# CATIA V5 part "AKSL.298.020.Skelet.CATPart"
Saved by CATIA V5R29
Part number: АКСЛ.298.000.Skelet
Publications: "S металла", "R гиба", "K factor", "OutputPlane.1 (Line.4)", "1 угол Profile.1", "2 угол Profile.2", "угол 1Profile.3", "угол 2Profile.4", "Extrude.1", "Extrude.2", "Profile.5", "Profile.6", "Plane.1", "Вертикальный уголок1 Sweep.1", "Вертикальный уголок2 Sweep.2", "ПЛТ середина вертикали Plane.9", "Положение ребра", "Отрезка Plane.11"
Bounding box of the stored display mesh (mm): x -250 to 300, y -300 to 52, z -248 to 52
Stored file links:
  Z:\ООО Аксель\Соединения бруса\Соединения бруса\Соединения из листа\АКСЛ.298.020 (Дуо)\AKSL.298.020.Skelet.CATPart
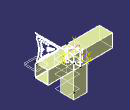
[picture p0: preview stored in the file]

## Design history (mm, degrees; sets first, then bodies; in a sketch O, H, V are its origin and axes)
Parameters
  `S металла` = 2 mm
  `R гиба` = 1.9 mm
  `K factor` = 0.49
  `Положение ребра` = 12 mm
Set1
  Extrude1: Element1 Sketch3.C1, Lim1 300, Lim2 100, Direction yz-plane, FirstUpto Plane2, SecondUpto Plane10
  Extrude2: Element1 Sketch3.C2, Lim1 300, Lim2 100, Direction yz-plane, FirstUpto Plane2, SecondUpto Plane10
  Plane1: type Offset, RefPlane yz-plane, Offset 52, reversed
  Plane2: type Offset, RefPlane Plane1, Offset 302
  Line1: type PtDir, RefPoint vertex [face of Extrude1], Direction zx-plane, Start 0, End 20
  Plane3: type 2Lines, Element1 Line1, Element2 edge of Extrude1
  Plane4: type Offset, RefPlane Plane3, Offset 12 {= `Положение ребра`}, reversed
  Sketch1 on Plane4, origin (0, 0, 40), H (1, 0, 0), V (0, 1, 0)
    line L1 (95.2986, -93.8989) -> (95.1702, -93.8708)
    line L2 (103.7348, -92.0951) -> (103.8404, -92.1505)
    line L3 (100.9137, -95.8319) -> (100.7931, -95.8772)
    line L4 (88.0721, -100.8486) -> (88.0277, -100.9705)
    line L5 (101.0187, -95.7527) -> (100.9137, -95.8319)
    circle A1 centre (68.6729, -176.9877) radius 4
    line L6 (87.0077, -111.8036) -> (86.7739, -111.2916)
    line L7 (75.3598, -82.5251) -> (75.142, -82.5472)
    line L8 (72.312, -80.0992) -> (72.247, -79.8958)
    line L9 (72.2211, -79.6855) -> (72.2342, -79.4741)
    line L10 (80.7946, -95.0346) -> (80.6807, -94.9619)
    line L11 (84.2807, -91.5755) -> (84.3166, -91.7324)
    line L12 (89.731, -91.801) -> (84.4045, -89.8059)
    line L13 (88.0384, -113.0845) -> (87.6445, -112.704)
    line L14 (83.0187, -99.498) -> (89.8948, -92.5474)
    line L15 (77.274, -85.8262) -> (77.3517, -85.7209)
    line L16 (91.1213, -114.1413) -> (90.5663, -114.1308)
    circle A2 centre (161.1601, -67.4127) radius 4
    line L17 (94.082, -112.8251) -> (93.6617, -113.1999)
    line L18 (103.9239, -92.227) -> (104.0205, -92.4228)
    line L19 (80.6807, -94.9619) -> (80.5861, -94.8608)
    line L20 (84.3067, -91.89) -> (84.2531, -92.0385)
    line L21 (94.921, -93.9256) -> (94.816, -94.0048)
    line L22 (88.1508, -100.7421) -> (88.0721, -100.8486)
    line L23 (108.5562, -90.1261) -> (108.3766, -90.0333)
    line L24 (83.8456, -90.0121) -> (83.8, -90.1301)
    line L25 (81.1886, -95.0686) -> (81.0549, -95.0893)
    line L26 (100.5369, -95.8592) -> (95.2986, -93.8989)
    line L27 (78.6809, -79.6446) -> (78.4822, -79.7363)
    line L28 (109.7605, -85.4744) -> (111.5707, -86.1022)
    line L29 (78.2968, -79.8563) -> (78.1279, -80.0039)
    line L30 (95.0417, -93.8803) -> (94.921, -93.9256)
    circle A3 centre (68.759, -192.9874) radius 4
    line L31 (90.0105, -92.3482) -> (90.0158, -92.1298)
    line L32 (227.6727, -52) -> (214.923, -71.1234)
    line L33 (79.8354, -83.3132) -> (79.9633, -83.3033)
    line L34 (78.1279, -80.0039) -> (75.9468, -82.2087)
    line L35 (95.1702, -93.8708) -> (95.0417, -93.8803)
    line L36 (104.0153, -92.6413) -> (103.9717, -92.746)
    line L37 (74.5134, -82.3628) -> (74.3336, -82.2176)
    circle A4 centre (141.0249, -107.9229) radius 4
    line L38 (80.5171, -94.7326) -> (77.2497, -86.203)
    line L39 (84.2531, -92.0385) -> (84.1575, -92.1683)
    circle A5 centre (108.8779, -140.4178) radius 4
    line L40 (91.7315, -108.3715) -> (91.8906, -108.2474)
    circle A6 centre (145.1604, -67.4988) radius 4
    line L41 (104.0205, -92.4228) -> (104.0153, -92.6413)
    line L42 (91.3701, -108.4755) -> (91.5551, -108.4469)
    line L43 (93.2043, -113.5149) -> (92.7158, -113.7683)
    circle A7 centre (177.1599, -67.3266) radius 4
    line L44 (88.0492, -101.2285) -> (90.6258, -107.9813)
    line L45 (108.8018, -90.4119) -> (108.6986, -90.2553)
    line L46 (91.0099, -108.3996) -> (91.1854, -108.4591)
    line L47 (77.2299, -85.9469) -> (77.274, -85.8262)
    line L48 (90.0092, -114.0498) -> (89.4664, -113.8998)
    line L49 (84.3166, -91.7324) -> (84.3067, -91.89)
    line L50 (72.559, -80.462) -> (72.416, -80.2899)
    line L51 (88.0277, -100.9705) -> (88.0194, -101.0997)
    line L52 (93.6617, -113.1999) -> (93.2043, -113.5149)
    circle A8 centre (96.5188, -154.9182) radius 4
    line L53 (87.2994, -112.2757) -> (87.0077, -111.8036)
    line L54 (74.924, -82.5276) -> (74.7123, -82.4661)
    line L55 (114.0524, -88.2338) -> (114.2803, -88.7469)
    arc A9 centre (434.9713, -430.8711) radius 421.7104 from (214.923, -71.1234) to (72.876, -214.7077) ccw
    line L56 (75.142, -82.5472) -> (74.924, -82.5276)
    line L57 (92.7158, -113.7683) -> (92.2019, -113.9584)
    line L58 (72.3779, -79.072) -> (72.5086, -78.8929)
    line L59 (80.5861, -94.8608) -> (80.5171, -94.7326)
    line L60 (114.3946, -91.5101) -> (114.2107, -92.032)
    line L61 (112.0966, -86.3219) -> (112.583, -86.6019)
    line L62 (83.9209, -89.9119) -> (83.8456, -90.0121)
    line L63 (112.583, -86.6019) -> (113.0259, -86.9377)
    line L64 (87.6445, -112.704) -> (87.2994, -112.2757)
    line L65 (90.8522, -108.2989) -> (91.0099, -108.3996)
    line L66 (89.4664, -113.8998) -> (88.9539, -113.6863)
    line L67 (113.2745, -93.4249) -> (94.082, -112.8251)
    line L68 (108.8827, -90.7719) -> (108.8638, -90.587)
    line L69 (79.7153, -83.3585) -> (79.8354, -83.3132)
    line L70 (79.6105, -83.4377) -> (79.7153, -83.3585)
    line L71 (88.4763, -113.4132) -> (88.0384, -113.0845)
    line L72 (129.436, -118.7603) -> (125.1706, -114.5406)
    line L73 (114.2803, -88.7469) -> (114.4442, -89.2929)
    line L74 (79.0417, -74.4774) -> (79.6558, -74.5617)
    line L75 (113.9617, -92.529) -> (113.649, -92.9953)
    line L76 (77.2497, -86.203) -> (77.2212, -86.0751)
    line L77 (92.2019, -113.9584) -> (91.6685, -114.0833)
    line L78 (76.143, -75.3051) -> (76.6695, -74.9799)
    line L79 (113.0259, -86.9377) -> (113.4211, -87.3246)
    line L80 (83.8205, -90.3962) -> (84.2807, -91.5755)
    line L81 (82.7295, -100.0335) -> (82.8343, -99.7476)
    circle A10 centre (155.3914, -95.4085) radius 4
    line L82 (72.876, -214.7077) -> (52, -233.3785)
    line L83 (90.0158, -92.1298) -> (89.9196, -91.9336)
    line L84 (78.4269, -74.4792) -> (79.0417, -74.4774)
    line L85 (114.2107, -92.032) -> (113.9617, -92.529)
    line L86 (108.3766, -90.0333) -> (79.7586, -79.6376)
    line L87 (100.7931, -95.8772) -> (100.6648, -95.8869)
    line L88 (79.3238, -79.5472) -> (79.105, -79.5493)
    circle A11 centre (193.1597, -67.2405) radius 4
    line L89 (78.4822, -79.7363) -> (78.2968, -79.8563)
    line L90 (79.6558, -74.5617) -> (80.2601, -74.734)
    line L91 (84.1377, -89.7883) -> (84.0202, -89.8353)
    line L92 (89.8363, -91.8567) -> (89.731, -91.801)
    line L93 (70.2496, -52) -> (227.6727, -52)
    line L94 (81.0549, -95.0893) -> (80.9215, -95.0775)
    line L95 (81.316, -95.014) -> (81.1886, -95.0686)
    line L96 (88.0194, -101.0997) -> (88.0492, -101.2285)
    line L97 (75.9468, -82.2087) -> (75.7687, -82.3558)
    line L98 (79.9633, -83.3033) -> (80.0914, -83.3305)
    line L99 (113.649, -92.9953) -> (113.2745, -93.4249)
    line L100 (90.6258, -107.9813) -> (90.7212, -108.1588)
    circle A12 centre (68.5007, -144.9881) radius 4
    line L101 (84.1575, -92.1683) -> (81.431, -94.9243)
    line L102 (108.6603, -91.2962) -> (108.7829, -91.1354)
    line L103 (114.4442, -89.2929) -> (114.538, -89.8548)
    line L104 (108.8638, -90.587) -> (108.8018, -90.4119)
    line L105 (72.2865, -79.2677) -> (72.3779, -79.072)
    line L106 (94.816, -94.0048) -> (88.1508, -100.7421)
    line L107 (108.8564, -90.9577) -> (108.8827, -90.7719)
    line L108 (82.7746, -100.6404) -> (82.7084, -100.3372)
    line L109 (108.6986, -90.2553) -> (108.5562, -90.1261)
    line L110 (80.0914, -83.3305) -> (103.7348, -92.0951)
    line L111 (114.5599, -90.4157) -> (114.5115, -90.9694)
    line L112 (52, -233.3785) -> (52, -70.3192)
    line L113 (79.105, -79.5493) -> (78.8896, -79.5821)
    circle A13 centre (84.8041, -169.944) radius 4
    line L114 (77.8206, -74.5649) -> (78.4269, -74.4792)
    line L115 (114.5115, -90.9694) -> (114.3946, -91.5101)
    circle A14 centre (129.1606, -67.585) radius 4
    line L116 (91.8906, -108.2474) -> (108.6603, -91.2962)
    circle A15 centre (68.4146, -128.9884) radius 4
    line L117 (80.9215, -95.0775) -> (80.7946, -95.0346)
    line L118 (74.7123, -82.4661) -> (74.5134, -82.3628)
    line L119 (80.2601, -74.734) -> (109.7605, -85.4744)
    line L120 (84.2677, -89.7765) -> (84.1377, -89.7883)
    line L121 (82.8343, -99.7476) -> (83.0187, -99.498)
    line L122 (90.7212, -108.1588) -> (90.8522, -108.2989)
    line L123 (84.0202, -89.8353) -> (83.9209, -89.9119)
    circle A16 centre (68.5868, -160.9879) radius 4
    line L124 (76.6695, -74.9799) -> (77.2317, -74.7325)
    line L125 (89.9196, -91.9336) -> (89.8363, -91.8567)
    line L126 (75.5708, -82.4613) -> (75.3598, -82.5251)
    line L127 (83.8, -90.1301) -> (83.7897, -90.2601)
    line L128 (72.416, -80.2899) -> (72.312, -80.0992)
    line L129 (72.2342, -79.4741) -> (72.2865, -79.2677)
    line L130 (108.7829, -91.1354) -> (108.8564, -90.9577)
    line L131 (113.7646, -87.7582) -> (114.0524, -88.2338)
    line L132 (103.8993, -92.8409) -> (101.0187, -95.7527)
    line L133 (77.2317, -74.7325) -> (77.8206, -74.5649)
    circle A17 centre (170.2902, -83.5327) radius 4
    arc A18 centre (120.2476, -119.5169) radius 7 from (125.1706, -114.5406) to (115.3245, -124.4932) ccw
    line L134 (74.3336, -82.2176) -> (72.559, -80.462)
    line L135 (83.7897, -90.2601) -> (83.8205, -90.3962)
    line L136 (77.2212, -86.0751) -> (77.2299, -85.9469)
    line L137 (100.6648, -95.8869) -> (100.5369, -95.8592)
    line L138 (91.5551, -108.4469) -> (91.7315, -108.3715)
    line L139 (114.538, -89.8548) -> (114.5599, -90.4157)
    arc A19 centre (124.513, -123.7366) radius 7 from (119.5899, -128.7129) to (129.436, -118.7603) ccw
    line L140 (90.5663, -114.1308) -> (90.0092, -114.0498)
    line L141 (91.1854, -108.4591) -> (91.3701, -108.4755)
    line L142 (103.8404, -92.1505) -> (103.9239, -92.227)
    line L143 (82.7084, -100.3372) -> (82.7295, -100.0335)
    line L144 (75.7687, -82.3558) -> (75.5708, -82.4613)
    line L145 (78.8896, -79.5821) -> (78.6809, -79.6446)
    line L146 (81.431, -94.9243) -> (81.316, -95.014)
    line L147 (89.9671, -92.4528) -> (90.0105, -92.3482)
    line L148 (89.8948, -92.5474) -> (89.9671, -92.4528)
    line L149 (113.4211, -87.3246) -> (113.7646, -87.7582)
    line L150 (72.5086, -78.8929) -> (75.6614, -75.7059)
    line L151 (115.3245, -124.4932) -> (119.5899, -128.7129)
    line L152 (79.5428, -79.5763) -> (79.3238, -79.5472)
    line L153 (88.9539, -113.6863) -> (88.4763, -113.4132)
    line L154 (79.7586, -79.6376) -> (79.5428, -79.5763)
    line L155 (91.6685, -114.0833) -> (91.1213, -114.1413)
    line L156 (86.7739, -111.2916) -> (82.7746, -100.6404)
    arc A20 centre (41.9463, -42.054) radius 30 from (52, -70.3192) to (70.2496, -52) ccw
    line L157 (84.4045, -89.8059) -> (84.2677, -89.7765)
    line L158 (103.9717, -92.746) -> (103.8993, -92.8409)
    line L159 (111.5707, -86.1022) -> (112.0966, -86.3219)
    line L160 (72.247, -79.8958) -> (72.2211, -79.6855)
    line L161 (75.6614, -75.7059) -> (76.143, -75.3051)
    line L162 (77.3517, -85.7209) -> (79.6105, -83.4377)
    point P1 (95.2986, -93.8989)
    point P2 (95.1702, -93.8708)
    point P3 (103.7348, -92.0951)
    point P4 (103.8404, -92.1505)
    point P5 (100.9137, -95.8319)
    point P6 (100.7931, -95.8772)
    point P7 (88.0721, -100.8486)
    point P8 (88.0277, -100.9705)
    point P9 (101.0187, -95.7527)
    point P10 (100.9137, -95.8319)
    point P11 (87.0077, -111.8036)
    point P12 (86.7739, -111.2916)
    point P13 (75.3598, -82.5251)
    point P14 (75.142, -82.5472)
    point P15 (72.312, -80.0992)
    point P16 (72.247, -79.8958)
    point P17 (72.2211, -79.6855)
    point P18 (72.2342, -79.4741)
    point P19 (80.7946, -95.0346)
    point P20 (80.6807, -94.9619)
    point P21 (84.2807, -91.5755)
    point P22 (84.3166, -91.7324)
    point P23 (89.731, -91.801)
    point P24 (84.4045, -89.8059)
    point P25 (88.0384, -113.0845)
    point P26 (87.6445, -112.704)
    point P27 (83.0187, -99.498)
    point P28 (89.8948, -92.5474)
    point P29 (77.274, -85.8262)
    point P30 (77.3517, -85.7209)
    point P31 (91.1213, -114.1413)
    point P32 (90.5663, -114.1308)
    point P33 (94.082, -112.8251)
    point P34 (93.6617, -113.1999)
    point P35 (103.9239, -92.227)
    point P36 (104.0205, -92.4228)
    point P37 (80.6807, -94.9619)
    point P38 (80.5861, -94.8608)
    point P39 (84.3067, -91.89)
    point P40 (84.2531, -92.0385)
    point P41 (94.921, -93.9256)
    point P42 (94.816, -94.0048)
    point P43 (88.1508, -100.7421)
    point P44 (88.0721, -100.8486)
    point P45 (108.5562, -90.1261)
    point P46 (108.3766, -90.0333)
    point P47 (83.8456, -90.0121)
    point P48 (83.8, -90.1301)
    point P49 (81.1886, -95.0686)
    point P50 (81.0549, -95.0893)
    point P51 (100.5369, -95.8592)
    point P52 (95.2986, -93.8989)
    point P53 (78.6809, -79.6446)
    point P54 (78.4822, -79.7363)
    point P55 (109.7605, -85.4744)
    point P56 (111.5707, -86.1022)
    point P57 (78.2968, -79.8563)
    point P58 (78.1279, -80.0039)
    point P59 (95.0417, -93.8803)
    point P60 (94.921, -93.9256)
    point P61 (90.0105, -92.3482)
    point P62 (90.0158, -92.1298)
    point P63 (214.923, -71.1234)
    point P64 (79.8354, -83.3132)
    point P65 (79.9633, -83.3033)
    point P66 (78.1279, -80.0039)
    point P67 (75.9468, -82.2087)
    point P68 (95.1702, -93.8708)
    point P69 (95.0417, -93.8803)
    point P70 (104.0153, -92.6413)
    point P71 (103.9717, -92.746)
    point P72 (74.5134, -82.3628)
    point P73 (74.3336, -82.2176)
    point P74 (80.5171, -94.7326)
    point P75 (77.2497, -86.203)
    point P76 (84.2531, -92.0385)
    point P77 (84.1575, -92.1683)
    point P78 (91.7315, -108.3715)
    point P79 (91.8906, -108.2474)
    point P80 (104.0205, -92.4228)
    point P81 (104.0153, -92.6413)
    point P82 (91.3701, -108.4755)
    point P83 (91.5551, -108.4469)
    point P84 (93.2043, -113.5149)
    point P85 (92.7158, -113.7683)
    point P86 (88.0492, -101.2285)
    point P87 (90.6258, -107.9813)
    point P88 (108.8018, -90.4119)
    point P89 (108.6986, -90.2553)
    point P90 (91.0099, -108.3996)
    point P91 (91.1854, -108.4591)
    point P92 (77.2299, -85.9469)
    point P93 (77.274, -85.8262)
    point P94 (90.0092, -114.0498)
    point P95 (89.4664, -113.8998)
    point P96 (84.3166, -91.7324)
    point P97 (84.3067, -91.89)
    point P98 (72.559, -80.462)
    point P99 (72.416, -80.2899)
    point P100 (88.0277, -100.9705)
    point P101 (88.0194, -101.0997)
    point P102 (93.6617, -113.1999)
    point P103 (93.2043, -113.5149)
    point P104 (87.2994, -112.2757)
    point P105 (87.0077, -111.8036)
    point P106 (74.924, -82.5276)
    point P107 (74.7123, -82.4661)
    point P108 (114.0524, -88.2338)
    point P109 (114.2803, -88.7469)
    point P110 (214.923, -71.1234)
    point P111 (72.876, -214.7077)
    point P112 (75.142, -82.5472)
    point P113 (74.924, -82.5276)
    point P114 (92.7158, -113.7683)
    point P115 (92.2019, -113.9584)
    point P116 (72.3779, -79.072)
    point P117 (72.5086, -78.8929)
    point P118 (80.5861, -94.8608)
    point P119 (80.5171, -94.7326)
    point P120 (114.3946, -91.5101)
    point P121 (114.2107, -92.032)
    point P122 (112.0966, -86.3219)
    point P123 (112.583, -86.6019)
    point P124 (83.9209, -89.9119)
    point P125 (83.8456, -90.0121)
    point P126 (112.583, -86.6019)
    point P127 (113.0259, -86.9377)
    point P128 (87.6445, -112.704)
    point P129 (87.2994, -112.2757)
    point P130 (90.8522, -108.2989)
    point P131 (91.0099, -108.3996)
    point P132 (89.4664, -113.8998)
    point P133 (88.9539, -113.6863)
    point P134 (113.2745, -93.4249)
    point P135 (94.082, -112.8251)
    point P136 (108.8827, -90.7719)
    point P137 (108.8638, -90.587)
    point P138 (79.7153, -83.3585)
    point P139 (79.8354, -83.3132)
    point P140 (79.6105, -83.4377)
    point P141 (79.7153, -83.3585)
    point P142 (88.4763, -113.4132)
    point P143 (88.0384, -113.0845)
    point P144 (129.436, -118.7603)
    point P145 (125.1706, -114.5406)
    point P146 (114.2803, -88.7469)
    point P147 (114.4442, -89.2929)
    point P148 (79.0417, -74.4774)
    point P149 (79.6558, -74.5617)
    point P150 (113.9617, -92.529)
    point P151 (113.649, -92.9953)
    point P152 (77.2497, -86.203)
    point P153 (77.2212, -86.0751)
    point P154 (92.2019, -113.9584)
    point P155 (91.6685, -114.0833)
    point P156 (76.143, -75.3051)
    point P157 (76.6695, -74.9799)
    point P158 (113.0259, -86.9377)
    point P159 (113.4211, -87.3246)
    point P160 (83.8205, -90.3962)
    point P161 (84.2807, -91.5755)
    point P162 (82.7295, -100.0335)
    point P163 (82.8343, -99.7476)
    point P164 (72.876, -214.7077)
    point P165 (90.0158, -92.1298)
    point P166 (89.9196, -91.9336)
    point P167 (78.4269, -74.4792)
    point P168 (79.0417, -74.4774)
    point P169 (114.2107, -92.032)
    point P170 (113.9617, -92.529)
    point P171 (108.3766, -90.0333)
    point P172 (79.7586, -79.6376)
    point P173 (100.7931, -95.8772)
    point P174 (100.6648, -95.8869)
    point P175 (79.3238, -79.5472)
    point P176 (79.105, -79.5493)
    point P177 (78.4822, -79.7363)
    point P178 (78.2968, -79.8563)
    point P179 (79.6558, -74.5617)
    point P180 (80.2601, -74.734)
    point P181 (84.1377, -89.7883)
    point P182 (84.0202, -89.8353)
    point P183 (89.8363, -91.8567)
    point P184 (89.731, -91.801)
    point P185 (81.0549, -95.0893)
    point P186 (80.9215, -95.0775)
    point P187 (81.316, -95.014)
    point P188 (81.1886, -95.0686)
    point P189 (88.0194, -101.0997)
    point P190 (88.0492, -101.2285)
    point P191 (75.9468, -82.2087)
    point P192 (75.7687, -82.3558)
    point P193 (79.9633, -83.3033)
    point P194 (80.0914, -83.3305)
    point P195 (113.649, -92.9953)
    point P196 (113.2745, -93.4249)
    point P197 (90.6258, -107.9813)
    point P198 (90.7212, -108.1588)
    point P199 (84.1575, -92.1683)
    point P200 (81.431, -94.9243)
    point P201 (108.6603, -91.2962)
    point P202 (108.7829, -91.1354)
    point P203 (114.4442, -89.2929)
    point P204 (114.538, -89.8548)
    point P205 (108.8638, -90.587)
    point P206 (108.8018, -90.4119)
    point P207 (72.2865, -79.2677)
    point P208 (72.3779, -79.072)
    point P209 (94.816, -94.0048)
    point P210 (88.1508, -100.7421)
    point P211 (108.8564, -90.9577)
    point P212 (108.8827, -90.7719)
    point P213 (82.7746, -100.6404)
    point P214 (82.7084, -100.3372)
    point P215 (108.6986, -90.2553)
    point P216 (108.5562, -90.1261)
    point P217 (80.0914, -83.3305)
    point P218 (103.7348, -92.0951)
    point P219 (114.5599, -90.4157)
    point P220 (114.5115, -90.9694)
    point P221 (79.105, -79.5493)
    point P222 (78.8896, -79.5821)
    point P223 (77.8206, -74.5649)
    point P224 (78.4269, -74.4792)
    point P225 (114.5115, -90.9694)
    point P226 (114.3946, -91.5101)
    point P227 (91.8906, -108.2474)
    point P228 (108.6603, -91.2962)
    point P229 (80.9215, -95.0775)
    point P230 (80.7946, -95.0346)
    point P231 (74.7123, -82.4661)
    point P232 (74.5134, -82.3628)
    point P233 (80.2601, -74.734)
    point P234 (109.7605, -85.4744)
    point P235 (84.2677, -89.7765)
    point P236 (84.1377, -89.7883)
    point P237 (82.8343, -99.7476)
    point P238 (83.0187, -99.498)
    point P239 (90.7212, -108.1588)
    point P240 (90.8522, -108.2989)
    point P241 (84.0202, -89.8353)
    point P242 (83.9209, -89.9119)
    point P243 (76.6695, -74.9799)
    point P244 (77.2317, -74.7325)
    point P245 (89.9196, -91.9336)
    point P246 (89.8363, -91.8567)
    point P247 (75.5708, -82.4613)
    point P248 (75.3598, -82.5251)
    point P249 (83.8, -90.1301)
    point P250 (83.7897, -90.2601)
    point P251 (72.416, -80.2899)
    point P252 (72.312, -80.0992)
    point P253 (72.2342, -79.4741)
    point P254 (72.2865, -79.2677)
    point P255 (108.7829, -91.1354)
    point P256 (108.8564, -90.9577)
    point P257 (113.7646, -87.7582)
    point P258 (114.0524, -88.2338)
    point P259 (103.8993, -92.8409)
    point P260 (101.0187, -95.7527)
    point P261 (77.2317, -74.7325)
    point P262 (77.8206, -74.5649)
    point P263 (125.1706, -114.5406)
    point P264 (115.3245, -124.4932)
    point P265 (74.3336, -82.2176)
    point P266 (72.559, -80.462)
    point P267 (83.7897, -90.2601)
    point P268 (83.8205, -90.3962)
    point P269 (77.2212, -86.0751)
    point P270 (77.2299, -85.9469)
    point P271 (100.6648, -95.8869)
    point P272 (100.5369, -95.8592)
    point P273 (91.5551, -108.4469)
    point P274 (91.7315, -108.3715)
    point P275 (114.538, -89.8548)
    point P276 (114.5599, -90.4157)
    point P277 (119.5899, -128.7129)
    point P278 (129.436, -118.7603)
    point P279 (90.5663, -114.1308)
    point P280 (90.0092, -114.0498)
    point P281 (91.1854, -108.4591)
    point P282 (91.3701, -108.4755)
    point P283 (103.8404, -92.1505)
    point P284 (103.9239, -92.227)
    point P285 (82.7084, -100.3372)
    point P286 (82.7295, -100.0335)
    point P287 (75.7687, -82.3558)
    point P288 (75.5708, -82.4613)
    point P289 (78.8896, -79.5821)
    point P290 (78.6809, -79.6446)
    point P291 (81.431, -94.9243)
    point P292 (81.316, -95.014)
    point P293 (89.9671, -92.4528)
    point P294 (90.0105, -92.3482)
    point P295 (89.8948, -92.5474)
    point P296 (89.9671, -92.4528)
    point P297 (113.4211, -87.3246)
    point P298 (113.7646, -87.7582)
    point P299 (72.5086, -78.8929)
    point P300 (75.6614, -75.7059)
    point P301 (115.3245, -124.4932)
    point P302 (119.5899, -128.7129)
    point P303 (79.5428, -79.5763)
    point P304 (79.3238, -79.5472)
    point P305 (88.9539, -113.6863)
    point P306 (88.4763, -113.4132)
    point P307 (79.7586, -79.6376)
    point P308 (79.5428, -79.5763)
    point P309 (91.6685, -114.0833)
    point P310 (91.1213, -114.1413)
    point P311 (86.7739, -111.2916)
    point P312 (82.7746, -100.6404)
    point P313 (84.4045, -89.8059)
    point P314 (84.2677, -89.7765)
    point P315 (103.9717, -92.746)
    point P316 (103.8993, -92.8409)
    point P317 (111.5707, -86.1022)
    point P318 (112.0966, -86.3219)
    point P319 (72.247, -79.8958)
    point P320 (72.2211, -79.6855)
    point P321 (75.6614, -75.7059)
    point P322 (76.143, -75.3051)
    point P323 (77.3517, -85.7209)
    point P324 (79.6105, -83.4377)
    construction line L163 (-62.6232, 0) -> (308.7345, 0)
    point P325 (-62.6232, 0)
    construction line L164 (0, 216.8539) -> (0, -307.4006)
    point P327 (0, 216.8539)
    curve C1
    curve C2
    distance L93 L163 = 52
    distance L112 L164 = 52
    coincidence: P325 H, P325 L71, P327 L104, P327 V, P164 P111, P110 P63, P51 P272, P52 P1, P271 P174, P173 P6, P5 P10, P9 P260, P259 P316, P315 P71, P70 P81, P80 P36, P35 P284, P283 P4, P3 P218, P217 P194, P193 P65, P64 P139, P138 P141, P140 P324, P323 P30, P29 P93, P92 P270, P269 P153, P152 P75, P74 P119, P118 P38, P37 P20, P19 P230, P229 P186, P185 P50, P49 P188, P187 P292, P291 P200, P199 P77, P76 P40, P39 P97, P96 P22, P21 P161, P160 P268, P267 P250, P249 P48, P47 P125, P124 P242, P241 P182, P181 P236, P235 P314, P313 P24, P23 P184, P183 P246, P245 P166, P165 P62, P61 P294, P293 P296, P295 P28, P27 P238, P237 P163, P162 P286, P285 P214, P213 P312, P311 P12, P11 P105, P104 P129, P128 P26, P25 P143, P142 P306, P305 P133, P132 P95, P94 P280, P279 P32, P31 P310, P309 P155, P154 P115, P114 P85, P84 P103, P102 P34, P33 P135, P134 P196, P195 P151, P150 P170, P169 P121, P120 P226, P225 P220, P219 P276, P275 P204, P203 P147, P146 P109, P108 P258, P257 P298, P297 P159, P158 P127, P126 P123, P122 P318, P317 P56, P55 P234, P233 P180, P179 P149, P148 P168, P167 P224, P223 P262, P261 P244, P243 P157, P156 P322, P321 P300, P299 P117, P116 P208, P207 P254, P253 P18, P17 P320, P319 P16, P15 P252, P251 P99, P98 P266, P265 P73, P72 P232, P231 P107, P106 P113, P112 P14, P13 P248, P247 P288, P287 P192, P191 P67, P66 P58, P57 P178, P177 P54, P53 P290, P289 P222, P221 P176, P175 P304, P303 P308, P307 P172, P171 P46, P45 P216, P215 P89, P88 P206, P205 P137, P136 P212, P211 P256, P255 P202, P201 P228, P227 P79, P78 P274, P273 P83, P82 P282, P281 P91, P90 P131, P130 P240, P239 P198, P197 P87, P86 P190, P189 P101, P100 P8, P7 P44, P43 P210, P209 P42, P41 P60, P59 P69, P68 P2, P277 P302, P278 P144, P301 P264, P263 P145
    horizontal: L163 H, L93 H
    vertical: L164 V, L112 V
  Plane5: type Between, Element1 Plane1, Element2 Plane2, Ratio 0.5
  Line2: type PtDir, LineFirstUpto Plane8, LineSecondUpto Plane7, RefPoint vertex of Sketch2, Direction xy-plane, Start -198, End -64
  Plane6: type 2Lines, Element1 edge [face of Extrude1 | face of Extrude1], Element2 edge of Extrude1
  Plane7 "ПЛТ горизонтакльной трубы Plane.7": type Offset, RefPlane Plane6, Offset 2 {= `S металла`}, reversed
  Plane8 "ПЛТ верхней трубы Plane.8": type Offset, RefPlane Plane7, Offset 196, reversed
  Sweep1 "Вертикальный уголок1 Sweep.1": type Unspec, Profile Sketch3.C1, Guide Line2
  Sweep2 "Вертикальный уголок2 Sweep.2": type Unspec, Profile Sketch3.C2, Guide Line2
  Plane9 "ПЛТ середина вертикали Plane.9": type Between, Element1 Plane7, Element2 Plane8, Ratio 0.5
  Plane10: type Offset, RefPlane Plane2, Offset 500, reversed
  Plane11 "Отрезка Plane.11": type Offset, RefPlane Plane2, Offset 2, reversed
Body1 (main body)
  Sketch2 on xy-plane, origin (0, 0, 0), H (1, 0, 0), V (0, 1, 0)
    line L1 (0, -300) -> (0, 0)
    point P1 (0, -300)
    line L2 (0, 0) -> (300, 0)
    point P2 (300, 0)
    construction line L3 through (0, 0) direction (-0.7071, 0.7071)
    curve C1
    curve C2
    curve C3
    construction line L4 (-29.6903, -29.6903) -> (76.691, 76.691)
    curve C4
    point P7 (0, 0)
    distance P1 L2 = 300
    distance L1 P2 = 300
    angle L4 L3 = 90
    coincidence: P1 V, L4 O, P7 O
    vertical: L1 V
    horizontal: L2 H
    symmetry: L1 L2 L3
  Sketch3 on yz-plane, origin (0, 0, 0), H (0, 1, 0), V (0, 0, 1)
    construction line L1 (50, 50) -> (50, -50)
    construction line L2 (50, -50) -> (-50, -50)
    construction line L3 (-50, -50) -> (-50, 50)
    construction line L4 (-50, 50) -> (50, 50)
    point P5 (-50, 52)
    line L5 (-50, 52) -> (-50, -50)
    line L6 (-50, -50) -> (50, -50)
    line L7 (-50, 50) -> (50, 50)
    line L8 (50, 50) -> (50, -52)
    point P6 (50, -52)
    curve C1
    curve C2
    construction line L9 (-50, 0) -> (50, 0)
    point P7 (-50, 0)
    point P8 (50, 0)
    construction line L10 (0, 50) -> (0, -50)
    point P9 (0, 50)
    point P10 (0, -50)
    point P11 (0, 0)
    distance L3 L1 = 100
    distance L4 L2 = 100
    distance P5 L4 = 2 {= `S металла`}
    distance P6 L6 = 2 {= `S металла`}
    vertical: L1 V, L3 V, L5 V, L8 V, L10 V
    horizontal: L2 H, L4 H, L6 H, L7 H, L9 H
    equidistance: L1 L3 O, L2 L4 O
    coincidence: P5 L3, P11 O
    midpoint: P7 L3, P8 L1, P9 L7, P10 L2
